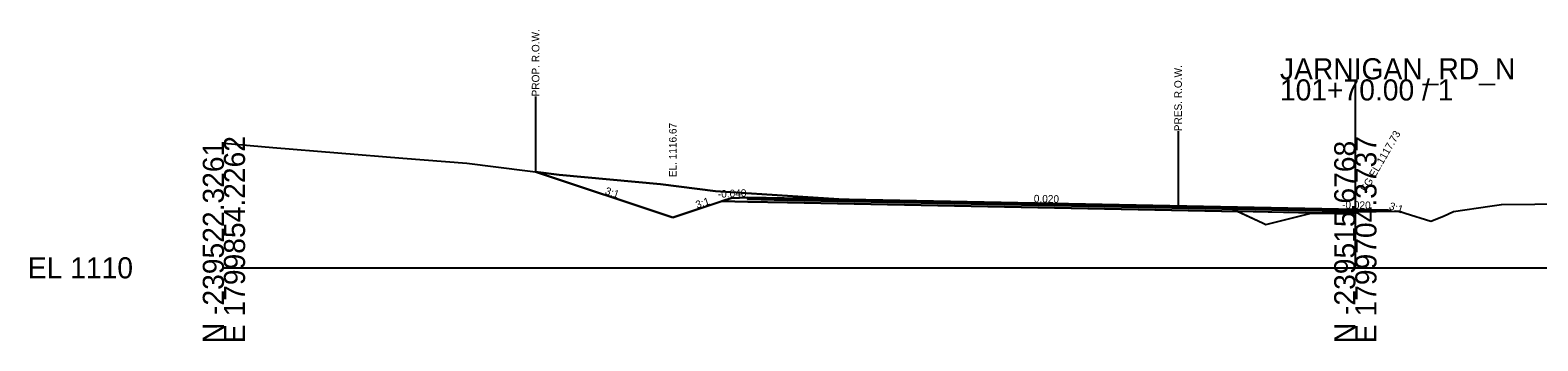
# Model space of a CAD drawing. Extents: x 214513 to 217151, y 214739 to 216780.
# Drawn here: x 216122.7 to 216322.6, y 215738.7 to 215779.9 of the extents above; entities that cross this region are included whole.
import ezdxf

# ---------------------------------------------------------------- set-up
doc = ezdxf.new("R2010")
doc.units = 0
for name, color, linetype in [('CONCEPT - TRANSPORTATION - Roads Text', 7, 'Continuous'), ('DESIGN - CENTERLINE - Proposed', 7, 'Continuous'), ('DESIGN - CENTERLINE - Proposed Text', 7, 'Continuous'), ('DESIGN - DRAINAGE - Special Ditches', 7, 'Continuous'), ('DESIGN - EARTHWORK - Shapes', 7, 'Continuous'), ('DESIGN - ROW - Right-of-Way Linework', 7, 'Continuous'), ('DESIGN - TRANSPORTATION - Text', 7, 'Continuous'), ('DESIGN - TYPICAL - Slope Tie Text', 7, 'Continuous'), ('Section', 7, 'Continuous'), ('SURVEY - DTM GRAPHICS - Triangles', 7, 'Continuous'), ('SURVEY - PROPERTY - ROW Lines', 7, 'Continuous'), ('XSCell', 7, 'Continuous')]:
    doc.layers.add(name, color=color, linetype=linetype)

msp = doc.modelspace()

# ---------------------------------------------------------------- linework, layer by layer
at = {"layer": 'DESIGN - DRAINAGE - Special Ditches'}
for points in [[(216207.87, 215755.03), (216189.66, 215761.1)], [(216215.63, 215757.62), (216207.87, 215755.03)], [(216217.8, 215757.71), (216217.8, 215757.46), (216223.09, 215757.35), (216298.36, 215755.84), (216298.36, 215755.51), (216223.09, 215757.02), (216217.8, 215757.13), (216214.36, 215757.19), (216215.63, 215757.62), (216217.8, 215757.71)], [(216298.36, 215756.09), (216217.8, 215757.71), (216217.8, 215757.61), (216217.8, 215757.61), (216298.36, 215755.99), (216298.36, 215755.99), (216298.36, 215755.99), (216298.36, 215756.09), (216298.36, 215756.09)], [(216298.36, 215755.99), (216217.8, 215757.61), (216217.8, 215757.46), (216217.8, 215757.46), (216298.36, 215755.84), (216298.36, 215755.84), (216298.36, 215755.84), (216298.36, 215755.99), (216298.36, 215755.99)], [(216298.36, 215756.09), (216298.36, 215755.99), (216298.36, 215755.99), (216300.51, 215755.95), (216300.51, 215755.95), (216300.51, 215756.05), (216298.36, 215756.09)], [(216300.51, 215756.05), (216302.68, 215756.01)], [(216302.68, 215756.01), (216303.1, 215755.87)]]:
    msp.add_lwpolyline(points, dxfattribs=at)
at = {"layer": 'DESIGN - EARTHWORK - Shapes'}
for p, q in [((216189.66, 215761.1), (216207.87, 215755.03)), ((216215.63, 215757.62), (216214.36, 215757.19)), ((216217.8, 215757.71), (216229.86, 215757.46)), ((216229.86, 215757.46), (216217.8, 215757.71)), ((216217.8, 215757.71), (216217.8, 215757.61)), ((216217.8, 215757.61), (216217.8, 215757.46)), ((216232.19, 215757.32), (216217.8, 215757.61)), ((216217.8, 215757.61), (216232.19, 215757.32)), ((216207.87, 215755.03), (216214.36, 215757.19)), ((216217.8, 215757.46), (216223.09, 215757.35)), ((216281.9, 215756.17), (216223.09, 215757.35)), ((216223.09, 215757.35), (216281.9, 215756.17)), ((216277.81, 215756.41), (216264.21, 215756.68)), ((216292.81, 215755.63), (216282.84, 215755.83)), ((216292.81, 215755.63), (216298.36, 215755.51)), ((216298.36, 215755.99), (216298.36, 215755.84)), ((216298.36, 215755.84), (216298.36, 215755.84)), ((216298.36, 215755.51), (216298.36, 215755.84)), ((216302.68, 215756.01), (216300.51, 215756.05)), ((216303.1, 215755.87), (216302.68, 215756.01))]:
    msp.add_line(p, q, dxfattribs=at)
for points in [[(216229.86, 215757.46), (216213.54, 215758.52), (216206.26, 215759.46), (216192.82, 215760.71), (216189.68, 215761.1), (216189.66, 215761.1)], [(216214.36, 215757.19), (216215.63, 215757.62), (216217.8, 215757.71)], [(216217.8, 215757.61), (216217.8, 215757.71), (216215.63, 215757.62)], [(216223.09, 215757.35), (216217.8, 215757.46), (216217.8, 215757.61)], [(216214.36, 215757.19), (216217.8, 215757.13), (216223.09, 215757.02), (216282.84, 215755.83)], [(216232.19, 215757.32), (216231.98, 215757.33), (216229.86, 215757.46)], [(216264.21, 215756.68), (216258.55, 215756.78), (216243.78, 215757.04), (216234.27, 215757.22), (216232.19, 215757.32)], [(216281.9, 215756.17), (216278.72, 215756.38), (216277.81, 215756.41)], [(216282.84, 215755.83), (216282.12, 215756.16), (216281.9, 215756.17)], [(216282.84, 215755.83), (216286.12, 215754.3), (216286.49, 215754.13), (216287.01, 215754.25), (216292.5, 215755.61), (216292.81, 215755.63)], [(216298.36, 215755.84), (216297.44, 215755.79), (216292.81, 215755.63)], [(216300.51, 215756.05), (216300.51, 215755.95), (216298.36, 215755.99)], [(216298.36, 215755.84), (216298.64, 215755.85), (216303.1, 215755.87)]]:
    msp.add_lwpolyline(points, dxfattribs=at)
at = {"layer": 'DESIGN - ROW - Right-of-Way Linework'}
msp.add_lwpolyline([(216189.68, 215771.1), (216189.68, 215761.1)], dxfattribs=at)
at = {"layer": 'SURVEY - DTM GRAPHICS - Triangles'}
msp.add_lwpolyline([(216148.36, 215764.88), (216154.83, 215764.32), (216172.09, 215762.9), (216180.55, 215762.24), (216192.82, 215760.71), (216206.26, 215759.46), (216213.54, 215758.52), (216231.98, 215757.33), (216234.27, 215757.22), (216243.78, 215757.04), (216258.55, 215756.78), (216274.51, 215756.49), (216278.72, 215756.38), (216282.12, 215756.16), (216286.12, 215754.3), (216286.49, 215754.13), (216287.01, 215754.25), (216292.5, 215755.61), (216297.44, 215755.79), (216298.64, 215755.85), (216303.52, 215755.87), (216304.23, 215755.88), (216304.98, 215755.62), (216308.38, 215754.56), (216310.03, 215755.22), (216311.36, 215755.82), (216316.2, 215756.52), (216317.75, 215756.76), (216322.17, 215756.81), (216326.67, 215756.86)], dxfattribs=at)
at = {"layer": 'SURVEY - PROPERTY - ROW Lines'}
msp.add_lwpolyline([(216274.86, 215766.48), (216274.86, 215756.48)], dxfattribs=at)
at = {"layer": 'XSCell'}
for p, q in [((216298.36, 215748.36), (216298.36, 215773.36)), ((216148.36, 215748.36), (216298.36, 215748.36)), ((216298.36, 215748.36), (216448.36, 215748.36))]:
    msp.add_line(p, q, dxfattribs=at)

# ---------------------------------------------------------------- texts
at = {"layer": 'CONCEPT - TRANSPORTATION - Roads Text'}
for s, rotation, p in [('-0.040', 2.2906, (216213.86, 215757.65)), ('0.020', 358.8542, (216255.72, 215757.05)), ('-0.020', 358.8542, (216296.59, 215756.23))]:
    msp.add_text(s, height=1, rotation=rotation, dxfattribs=at).set_placement(p)
at = {"layer": 'DESIGN - CENTERLINE - Proposed'}
msp.add_text('EL. 1116.67', height=1, rotation=90, dxfattribs=at).set_placement((216208.37, 215760.38))
at = {"layer": 'DESIGN - CENTERLINE - Proposed Text'}
msp.add_text('FG EL.1117.73', height=1, rotation=60, dxfattribs=at).set_placement((216299.86, 215758.33))
at = {"layer": 'DESIGN - TRANSPORTATION - Text'}
for s, p in [('PROP. R.O.W.', (216190.18, 215771.1)), ('PRES. R.O.W.', (216275.36, 215766.48))]:
    msp.add_text(s, height=1, rotation=90, dxfattribs=at).set_placement(p)
at = {"layer": 'DESIGN - TYPICAL - Slope Tie Text'}
for rotation, p in [(341.5651, (216198.8, 215758.16)), (18.4349, (216211.09, 215756.21)), (341.5652, (216302.74, 215756.16))]:
    msp.add_text('3:1', height=1, rotation=rotation, dxfattribs=at).set_placement(p)
at = {"layer": 'Section'}
msp.add_text('-', height=0.0001, dxfattribs=at).set_placement((216148.36, 215748.36))
at = {"layer": 'XSCell'}
for s, p in [('JARNIGAN_RD_N', (216288.36, 215773.36)), ('101+70.00 / 1', (216288.36, 215770.56)), ('EL 1110', (216122.36, 215746.96))]:
    msp.add_text(s, height=2.8, dxfattribs=at).set_placement(p)
for s, p in [('E 1799854.2262', (216151.16, 215738.36)), ('E 1799704.3737', (216301.16, 215738.36)), ('N -239522.3261', (216148.36, 215738.36)), ('N -239515.6768', (216298.36, 215738.36))]:
    msp.add_text(s, height=2.8, rotation=90, dxfattribs=at).set_placement(p)

doc.saveas('drawing.dxf')
